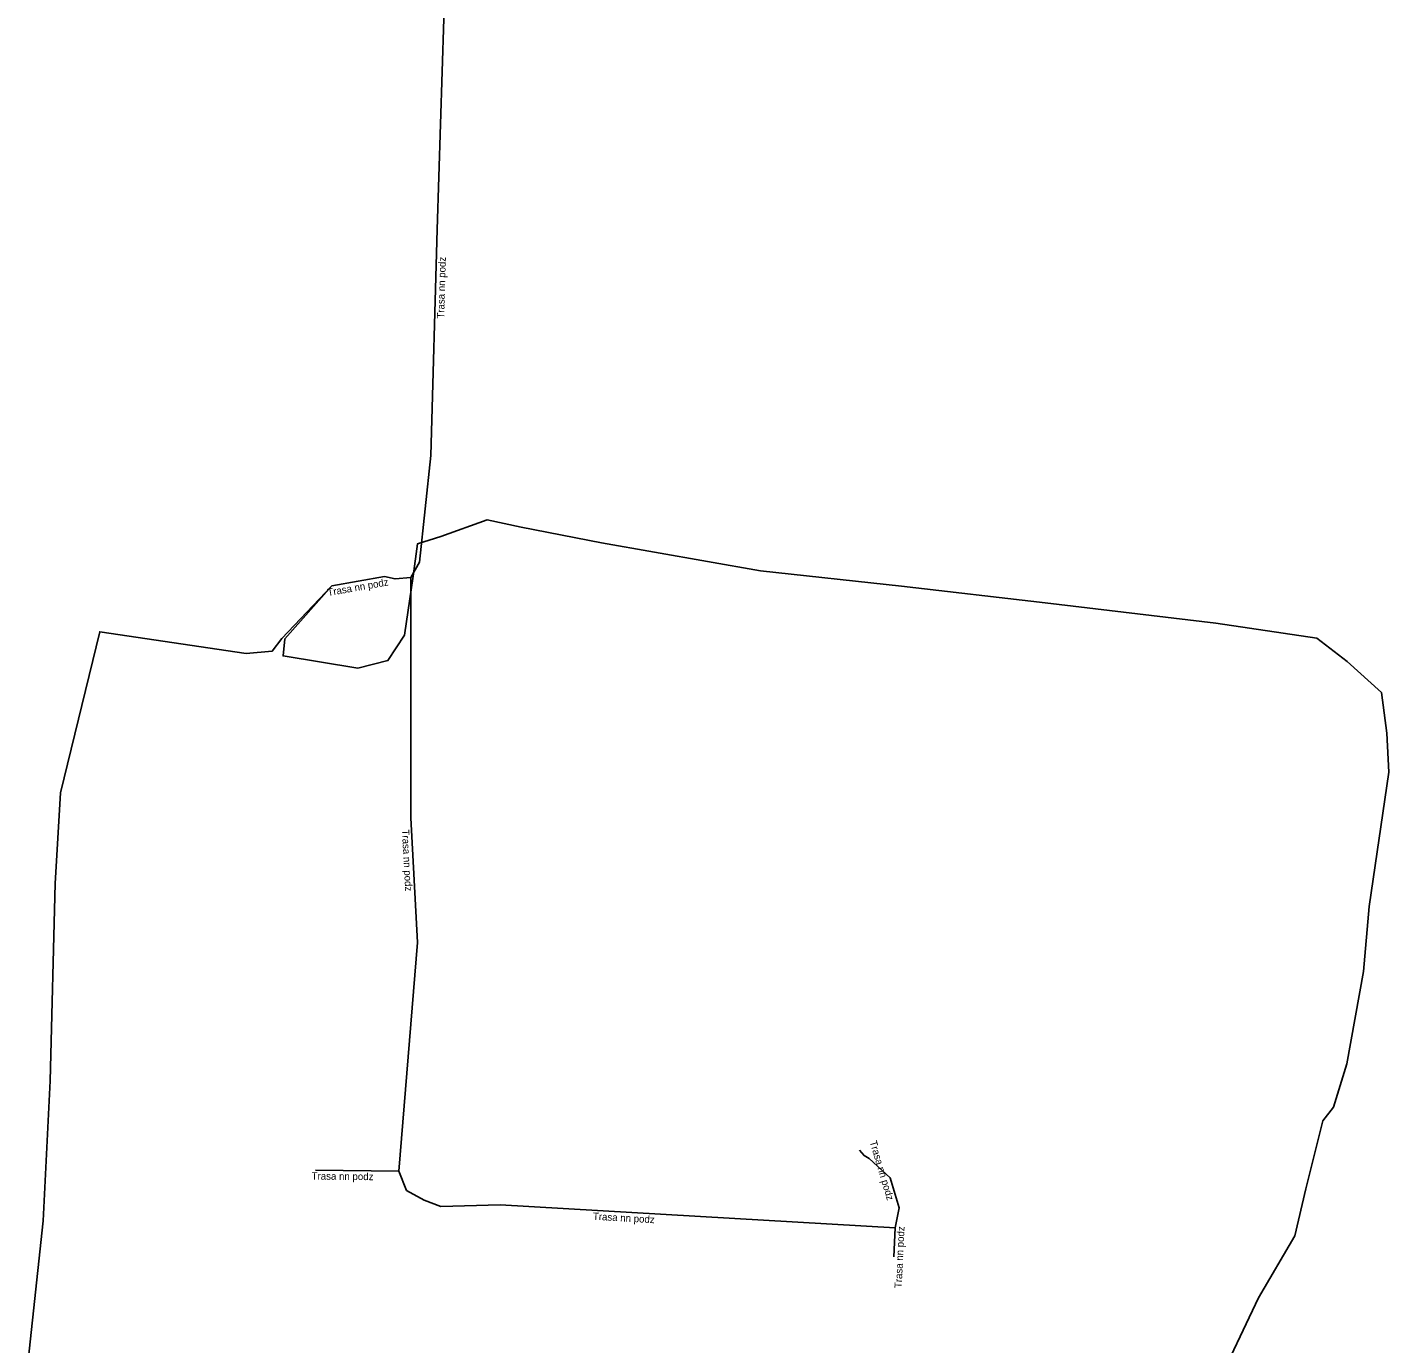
# Model space of a CAD drawing. Extents: x -682739 to -681564, y -1060091 to -1059590.
# Drawn here: x -682111.3 to -682017.2, y -1059876.8 to -1059785.7 of the extents above; entities that cross this region are included whole.
import ezdxf

# ---------------------------------------------------------------- set-up
doc = ezdxf.new("R2010")
doc.units = 0
for name, color, linetype in [('Popiskový text - Ostatní atributy Trasy', 7, 'Continuous'), ('Spojnice NN', 7, 'Continuous'), ('Spojnice VN', 7, 'Continuous')]:
    doc.layers.add(name, color=color, linetype=linetype)

msp = doc.modelspace()

# ---------------------------------------------------------------- linework, layer by layer
at = {"layer": 'Spojnice NN'}
for points in [[(-682082.4, -1059781.44), (-682082.96, -1059799.69), (-682083.41, -1059815.33), (-682084.2, -1059822.7), (-682084.78, -1059823.76)], [(-682084.78, -1059823.76), (-682085.88, -1059823.86), (-682086.62, -1059823.7), (-682090.266, -1059824.348)], [(-682084.78, -1059823.76), (-682084.8, -1059840.4), (-682084.34, -1059849.02), (-682085.61, -1059864.83)], [(-682051.3, -1059868.75), (-682051.029, -1059867.363), (-682051.644, -1059865.296), (-682053.1, -1059863.95), (-682053.44, -1059863.76), (-682053.76, -1059863.39)], [(-682085.61, -1059864.83), (-682091.39, -1059864.766)], [(-682085.61, -1059864.83), (-682085.08, -1059866.17), (-682083.87, -1059866.85), (-682082.71, -1059867.27), (-682078.61, -1059867.17), (-682051.3, -1059868.75)], [(-682051.3, -1059868.75), (-682051.396, -1059870.762)]]:
    msp.add_lwpolyline(points, dxfattribs=at)
at = {"layer": 'Spojnice VN'}
for points in [[(-682090.266, -1059824.348), (-682093.51, -1059828.01), (-682093.63, -1059829.19), (-682088.45, -1059830.03), (-682086.38, -1059829.51), (-682085.24, -1059827.76), (-682084.63, -1059823.68), (-682084.33, -1059821.43), (-682082.72, -1059820.93), (-682079.51, -1059819.78), (-682077.16, -1059820.29), (-682071.6, -1059821.37), (-682060.6, -1059823.31), (-682050.86, -1059824.36), (-682040.92, -1059825.51), (-682029.13, -1059826.93), (-682022.13, -1059827.96), (-682020.04, -1059829.57), (-682017.67, -1059831.72), (-682017.3, -1059834.54), (-682017.16, -1059837.22), (-682018.52, -1059846.52), (-682018.9, -1059851.03), (-682020.07, -1059857.41), (-682020.99, -1059860.4), (-682021.73, -1059861.35), (-682022.89, -1059866.05), (-682023.65, -1059869.31), (-682026.16, -1059873.6), (-682029.14, -1059879.88)], [(-682111.32, -1059878.57), (-682110.21, -1059868.27), (-682109.73, -1059858.58), (-682109.38, -1059844.93), (-682109.03, -1059838.65), (-682106.303, -1059827.515), (-682096.17, -1059829.03), (-682094.37, -1059828.85), (-682093.71, -1059827.99), (-682090.266, -1059824.348)]]:
    msp.add_lwpolyline(points, dxfattribs=at)

# ---------------------------------------------------------------- texts
at = {"layer": 'Popiskový text - Ostatní atributy Trasy'}
for rotation, p in [(88.35192, (-682082.488, -1059805.858)), (10.07654, (-682090.512, -1059825.052)), (273.05465, (-682085.407, -1059841.212)), (286.56946, (-682053.063, -1059862.803)), (359.36561, (-682091.654, -1059865.413)), (356.68889, (-682072.21, -1059868.192)), (87.26828, (-682050.848, -1059872.931))]:
    msp.add_text('Trasa nn podz', height=0.5, rotation=rotation, dxfattribs=at).set_placement(p)

doc.saveas('drawing.dxf')
